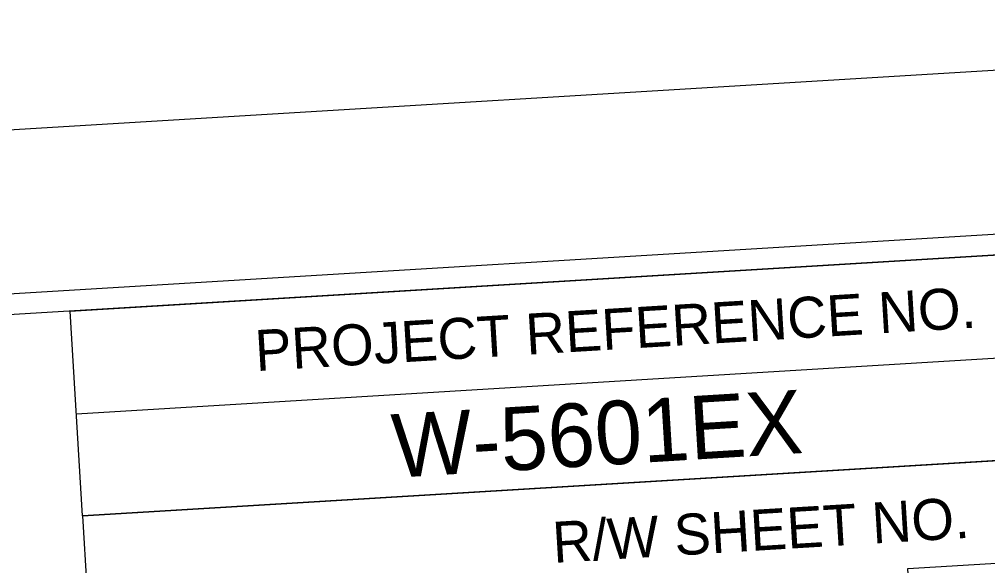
# Model space of a CAD drawing. Extents: x 2111349 to 2114115, y 669753 to 671326.
# Drawn here: x 2113627.8 to 2113745.9, y 670880.9 to 670947.5 of the extents above; entities that cross this region are included whole.
import ezdxf

# ---------------------------------------------------------------- set-up
doc = ezdxf.new("R2010")
doc.units = 0
for name, color, linetype in [('Exist Roads Curbs', 7, 'Continuous'), ('Exist Roads Curbs Text', 7, 'Continuous'), ('Exist Roads EOP Other Text', 7, 'Continuous'), ('Exist Utilities Telephone Test Hole SUE LOS A Text', 7, 'Continuous'), ('Exist Utilities Water Test Hole SUE LOS A Text', 7, 'Continuous')]:
    doc.layers.add(name, color=color, linetype=linetype)

msp = doc.modelspace()

# ---------------------------------------------------------------- linework, layer by layer
at = {"layer": 'Exist Roads Curbs'}
msp.add_line((2113849.32, 670947.55), (2112168.9, 670845.7), dxfattribs=at)
at = {"layer": 'Exist Roads Curbs Text'}
for p, q in [((2113634.78, 670899.43), (2113834.47, 670911.53)), ((2113635.54, 670886.95), (2113835.22, 670899.06)), ((2113635.54, 670886.95), (2113636.3, 670874.48))]:
    msp.add_line(p, q, dxfattribs=at)
for points in [[(2113833.71, 670924.06), (2112336.45, 670833.32), (2112399.97, 669785.24), (2113897.23, 669875.98)], [(2113634.02, 670911.96), (2113833.71, 670924.06), (2113835.22, 670899.06), (2113635.54, 670886.95)], [(2113736.16, 670880.53), (2113835.98, 670886.58), (2113842.78, 670774.29), (2113742.97, 670768.24)]]:
    msp.add_lwpolyline(points, close=True, dxfattribs=at)
at = {"layer": 'Exist Roads EOP Other Text'}
msp.add_lwpolyline([(2112246.91, 669773.46), (2113909.86, 669874.24), (2113846.03, 670927.31), (2112183.08, 670826.53)], close=True, dxfattribs=at)
at = {"layer": 'Exist Utilities Water Test Hole SUE LOS A Text'}
msp.add_lwpolyline([(2112235.14, 669752.71), (2113915.56, 669854.55), (2113849.32, 670947.55), (2112168.9, 670845.7)], close=True, dxfattribs=at)

# ---------------------------------------------------------------- texts
at = {"layer": 'Exist Roads Curbs Text'}
for s, p in [('PROJECT REFERENCE NO.', (2113656.71, 670904.62)), ('R/W SHEET NO.', (2113692.99, 670881.22))]:
    msp.add_text(s, height=5.0001, rotation=3.4682, dxfattribs=at).set_placement(p)
at = {"layer": 'Exist Utilities Telephone Test Hole SUE LOS A Text'}
msp.add_text('W-5601EX', height=7.75, rotation=3.4682, dxfattribs=at).set_placement((2113673.5, 670891.61))

doc.saveas('drawing.dxf')
